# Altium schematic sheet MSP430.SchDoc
size A; SheetNumber: roneV11-msp430; SheetTotal: 6
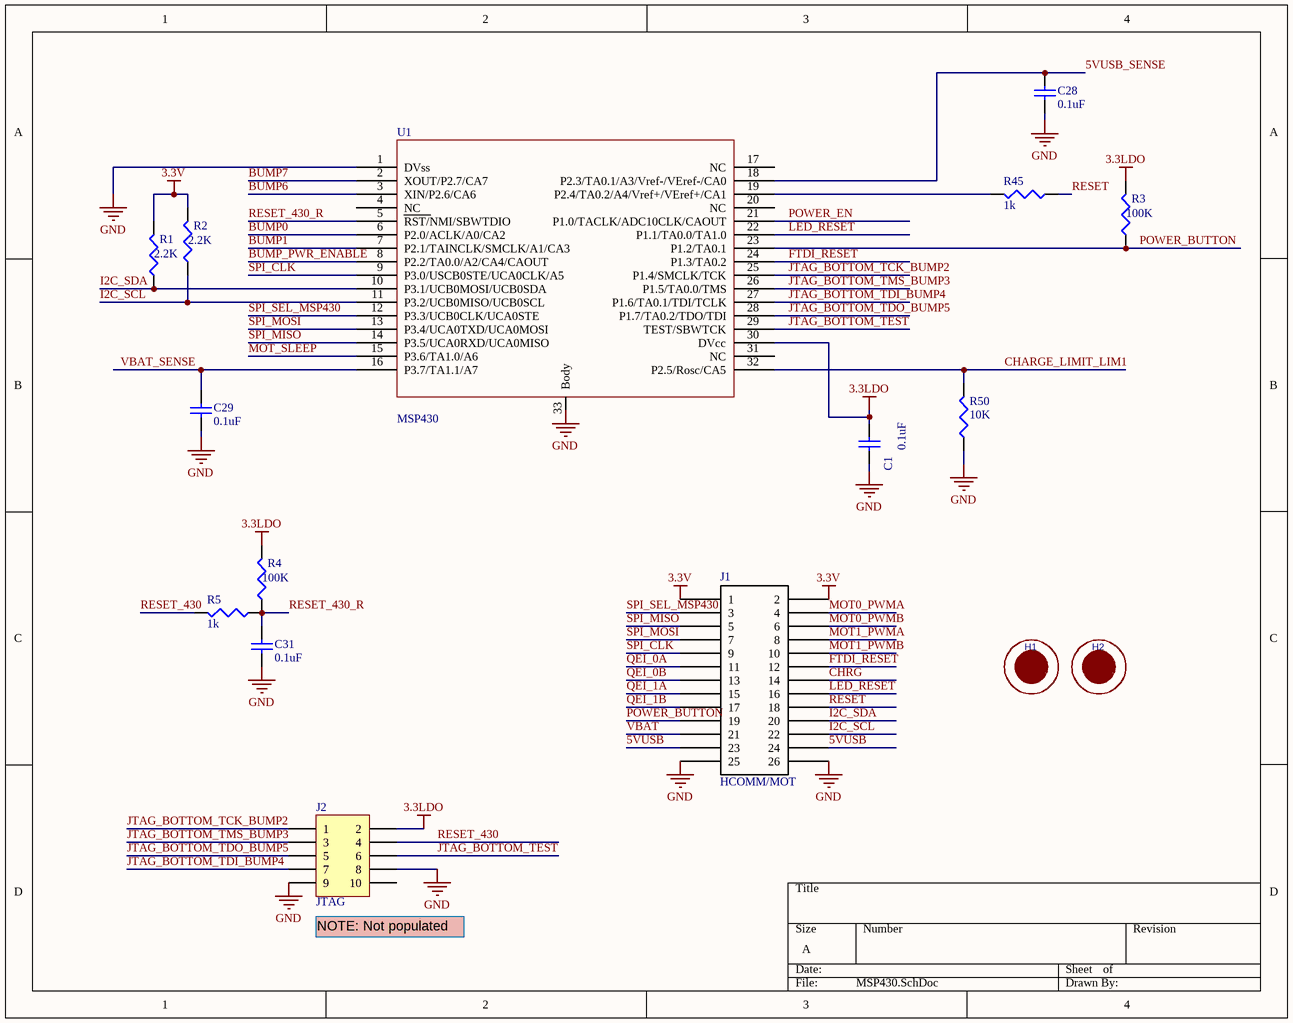
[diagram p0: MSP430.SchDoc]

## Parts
C1  value 0.1uF  [CAPC1005L]  (hidden comment: Cap Semi)
C28  value 0.1uF  [CAPC1005L]  (hidden comment: Cap Semi)
C29  value 0.1uF  [CAPC1005L]  (hidden comment: Cap Semi)
C31  value 0.1uF  [CAPC1005L]  (hidden comment: Cap Semi)
H1  H_FID_F40  [F40]  (value not drawn)
H2  H_FID_F40  [F40]  (value not drawn)
J1  HCOMM/MOT  [HeaderSM 13x2]
J2  JTAG  [HDR2X5]
R1  value 2.2K  [RESC1608L]  (hidden comment: Res3)
R2  value 2.2K  [RESC1608L]  (hidden comment: Res3)
R3  value 100K  [RESC1608L]  (hidden comment: Res3)
R4  value 100K  [RESC1608L]  (hidden comment: Res3)
R5  value 1k  [RESC1608L]  (hidden comment: Res3)
R45  value 1k  [RESC1608L]  (hidden comment: Res3)
R50  value 10K  [RESC1608L]  (hidden comment: Res3)
U1  MSP430  [MSP430_32PIN]

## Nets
3.3LDO: C1.2 J2.2 R3.2 R4.2 U1.30(DVcc)
3.3V: J1.1 J1.2 R1.2 R2.2
GND: C1.1 C28.1 C29.1 C31.1 J1.25 J1.26 J2.8 J2.9 R50.1 U1.1(DVss) U1.33(Body)
5VUSB: J1.23 J1.24
5VUSB_SENSE: C28.2 U1.18(P2.3/TA0.1/A3/Vref-/VEref-/CA0)
BUMP0: U1.6(P2.0/ACLK/A0/CA2)
BUMP1: U1.7(P2.1/TAINCLK/SMCLK/A1/CA3)
BUMP6: U1.3(XIN/P2.6/CA6)
BUMP7: U1.2(XOUT/P2.7/CA7)
BUMP_PWR_ENABLE: U1.8(P2.2/TA0.0/A2/CA4/CAOUT)
CHARGE_LIMIT_LIM1: R50.2 U1.32(P2.5/Rosc/CA5)
CHRG: J1.14
FTDI_RESET: J1.12 U1.24(P1.3/TA0.2)
I2C_SCL: J1.22 R2.1 U1.11(P3.2/UCB0MISO/UCB0SCL)
I2C_SDA: J1.20 R1.1 U1.10(P3.1/UCB0MOSI/UCB0SDA)
JTAG_BOTTOM_TCK_BUMP2: J2.1 U1.25(P1.4/SMCLK/TCK)
JTAG_BOTTOM_TDI_BUMP4: J2.7 U1.27(P1.6/TA0.1/TDI/TCLK)
JTAG_BOTTOM_TDO_BUMP5: J2.5 U1.28(P1.7/TA0.2/TDO/TDI)
JTAG_BOTTOM_TEST: J2.6 U1.29(TEST/SBWTCK)
JTAG_BOTTOM_TMS_BUMP3: J2.3 U1.26(P1.5/TA0.0/TMS)
LED_RESET: J1.16 U1.22(P1.1/TA0.0/TA1.0)
MOT0_PWMA: J1.4
MOT0_PWMB: J1.6
MOT1_PWMA: J1.8
MOT1_PWMB: J1.10
MOT_SLEEP: U1.15(P3.6/TA1.0/A6)
POWER_BUTTON: J1.19 R3.1 U1.23(P1.2/TA0.1)
POWER_EN: U1.21(P1.0/TACLK/ADC10CLK/CAOUT)
QEI_0A: J1.11
QEI_0B: J1.13
QEI_1A: J1.15
QEI_1B: J1.17
RESET: J1.18 R45.1
RESET_430: J2.4 R5.2
RESET_430_R: C31.2 R4.1 R5.1 U1.5(RST/NMI/SBWTDIO)
SPI_CLK: J1.9 U1.9(P3.0/USCB0STE/UCA0CLK/A5)
SPI_MISO: J1.5 U1.14(P3.5/UCA0RXD/UCA0MISO)
SPI_MOSI: J1.7 U1.13(P3.4/UCA0TXD/UCA0MOSI)
SPI_SEL_MSP430: J1.3 U1.12(P3.3/UCB0CLK/UCA0STE)
VBAT: J1.21
VBAT_SENSE: C29.2 U1.16(P3.7/TA1.1/A7)
NetR45_2: R45.2 U1.19(P2.4/TA0.2/A4/Vref+/VEref+/CA1)

Not connected (* = marked no-connect by the designer): H1 1; H2 1; J2 10; U1 4(NC) 17(NC) 20(NC) 31(NC)

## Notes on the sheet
- (near J2) NOTE: Not populated

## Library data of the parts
C1 C28 C29 C31 = Cap Semi: Capacitor (Semiconductor SIM Model); Part Number: GRM155R71C104KA88D; Manufacturer: Murata
H1 H2 = H00083: FabLevel: Intrinsic; CPN: H00083; Rule: UNIONINDEX{}0[]RULEKIND{}ComponentClearance[]NETSCOPE{}AnyNet[]LAYERKIND{}SameLayer[]NAME{}Schematic Component Clearance Constraint[]GAP{}0.5mil[]COLLISIONCHECKMODE{}3[]VERTICALGAP{}10mil[]SHOWDISTANCES{}FALSE[]UNIT{}Imperial[]PcbType{}ProtelPcb; Title: Fiducial 0.040" - Helps assembly machines locate parts; Category Letter: H
J1 = HCOMM/HMOT: Header, 2X20, 50mil, IDC; Part Number: SHF-113-01-l-E-SM-LC; Manufacturer: Samtec
J2 = Header 5X2: Header, 5-Pin, Dual row
R1 R2 = Res3: Resistor; Part Number: ERJ-3GEYJ-222V; Manufacturer: Panasonic
R3 R4 = Res3: Resistor; Part Number: ERJ-3GEYJ104V; Manufacturer: Panasonic
R5 R45 = Res3: Resistor; Part Number: ERJ-3GEYJ102V; Manufacturer: Panasonic
R50 = Res3: Resistor; Part Number: 71-CRCW0603-10K-E3; Manufacturer: Vishay Dale
U1 = MSP430_32pin: Part Number: MSP430F2132IRHBR; Manufacturer: TI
